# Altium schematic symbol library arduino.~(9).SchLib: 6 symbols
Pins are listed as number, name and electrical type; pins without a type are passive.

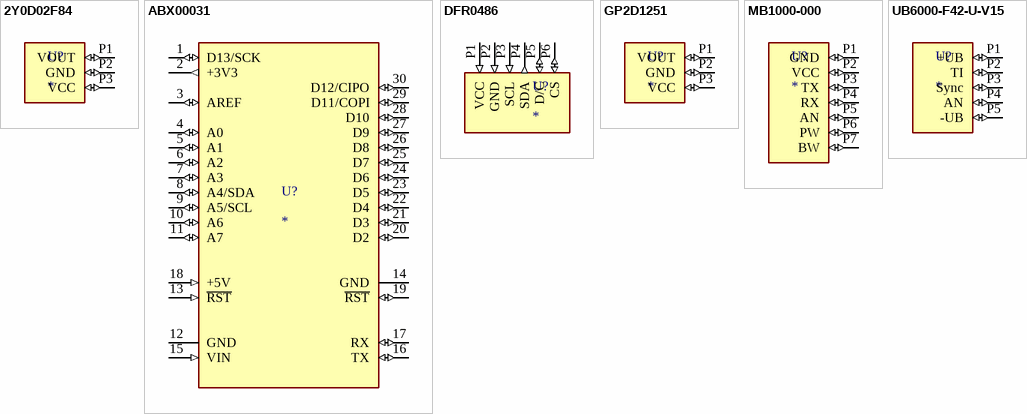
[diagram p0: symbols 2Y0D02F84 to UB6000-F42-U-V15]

## 2Y0D02F84
designator U?
SENSOR OPTICAL ANALOG; MP: GP2D120; MF: Sharp
footprint GP2DXX
pins: P1 VOUT (io), P2 GND (io), P3 VCC (io)

## ABX00031
designator U?
Arduino Nano 33 BLE; MP: ABX00030
footprint MODULE_ABX00030
pins: 1 D13/SCK (io), 2 +3V3 (out), 3 AREF (io), 4 A0 (io), 5 A1 (io), 6 A2 (io), 7 A3 (io), 8 A4/SDA (io), 9 A5/SCL (io), 10 A6 (io), 11 A7 (io), 12 GND (power), 13 ~{RST} (in), 14 GND (power), 15 VIN (in), 16 TX (io), 17 RX (io), 18 +5V (in), 19 ~{RST} (io), 20 D2 (io), 21 D3 (io), 22 D4 (io), 23 D5 (io), 24 D6 (io), 25 D7 (io), 26 D8 (io), 27 D9 (io), 28 D10 (io), 29 D11/COPI (io), 30 D12/CIPO (io)

## DFR0486
designator U?
0.96" 128x64 OLED(V1.0) display DFROBOT; MP: GP2D120; MF: Sharp
footprint GP2DXX
pins: P1 VCC (in), P2 GND (in), P3 SCL (in), P4 SDA (out), P5 D/C (io), P6 CS (io)

## GP2D1251
designator U?
SENSOR OPTICAL ANALOG; MP: GP2D120; MF: Sharp
footprint GP2DXX
pins: P1 VOUT (io), P2 GND (io), P3 VCC (io)

## MB1000-000
designator U?
Analog ultrasonic sensor; MP: GP2D120; MF: Sharp
footprint GP2DXX
pins: P1 GND (io), P2 VCC (io), P3 TX (io), P4 RX (io), P5 AN (io), P6 PW (io), P7 BW (io)

## UB6000-F42-U-V15
designator U?
Ultrasonic sensor; MP: GP2D120; MF: Sharp
footprint GP2DXX
pins: P1 +UB (io), P2 TI (io), P3 Sync (io), P4 AN (io), P5 -UB (io)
